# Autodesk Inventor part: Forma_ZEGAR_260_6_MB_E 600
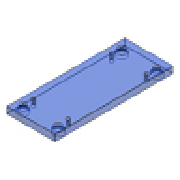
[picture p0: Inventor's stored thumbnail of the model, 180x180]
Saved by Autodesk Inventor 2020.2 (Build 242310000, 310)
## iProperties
Manager: www.cadconsulting.pl
Company: Fabian Stasiak CAD Consulting
Created: 2014-02
Part Number: Forma_ZEGAR_260_6_MB_E 600
Material: S 55 C
Description: Ejector Retainer Plate
Document SubType Name: Modeling
Designer: F.Stasiak
Standard Revision: 1
Manufacturer: DME
Language: pl-PL
Size Designation: 496x218x17
Categories: <MemberInstance><Categories><Category DisplayName="Forma wtryskowa" InternalName="349578f2-f4d4-4954-8c09-8e99297a61c0" Mnemonic="MOLD"><Category DisplayName="P
Density: 7.85 g/cm^3
Appearance: Clear - Blue
Catalog Web Link: www.expertbooks.pl
IsCustomPart: 1
Author: F.Stasiak
Subject: Zbiór ćwiczeń. Autodesk Inventor 2020. Kurs Professional
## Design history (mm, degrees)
sketch "Sketch1"
  geometry: L1 (-109, 248)-(109, 248); L2 (109, 248)-(109, -248); L3 (109, -248)-(-109, -248); L4 (-109, -248)-(-109, 248); 5 further points
  constraints: 8 end point, 2 midpoint, 2 parallel, 1 horizontal, 1 horizontal alignment, 1 perpendicular, 1 vertical alignment
  dimensions: "d84" = 218 distance between parallel lines of L2 L4 (= W_); "d85" = 496 distance between parallel lines of L3 L1 (= L); "d86" = 95 horizontal distance of point (0, 0) point (-95, 233) (= 0.5 x RP_W); "d87" = 233 vertical distance of point (0, 0) point (-95, 233) (= 0.5 x RP_L); "d88" = 95 horizontal distance of point (0, 0) point (-95, 210) (= 0.5 x S2_W); "d89" = 210 vertical distance of point (0, 0) point (-95, 210) (= 0.5 x S2_L)
extrude "Extrusion1" new body sketch "Sketch1" distance "d20" = 17 (= H_); taper "d30" = 0 deg
hole "Hole1" sketch "Sketch1" diameter "d90" = 8.376; stored, may be unused: countersink angle "d94" = 90 deg, drill point angle "d96" = 0 deg; dims "d91" = 6, "d92" = 4, "d93" = 2, "d95" = 17 (= H_)
pattern_linear "Rectangular Pattern1" dims "d106" = 420 (computed from S2_L, Nl), "d109" = 190 (computed from S2_W, Nw)
hole "Hole2" sketch "Sketch1" diameter "d97" = 14 (= RP_d1); stored, may be unused: countersink angle "d101" = 90 deg, drill point angle "d103" = 0 deg; dims "d98" = 6, "d99" = 19 (= RP_d2), "d100" = 4 (= RP_k), "d102" = 17 (= H_)
pattern_linear "Rectangular Pattern2" dims "d112" = 466 (computed from RP_L, Nl), "d115" = 190 (computed from RP_W, Nw)
chamfer "Chamfer1" distance "d116" = 0.5; stored, may be unused: second distance "d117" = 2, angle "d118" = 45 deg
sketch "Szkic13"
  geometry: 1 further point
hole "Otwór19" sketch "Szkic13" at (0, 0) diameter "d196" = 4.5; stored, may be unused: countersink angle "d200" = 90 deg, drill point angle "d202" = 0 deg; dims "d197" = 6, "d198" = 8, "d199" = 3, "d201" = 8
sketch "Szkic14"
  geometry: 4 further points
hole "Otwór20" sketch "Szkic14" at (-54, 134), (-24, -134), (24, 134), (54, -134) diameter "d203" = 5; stored, may be unused: countersink angle "d207" = 90 deg, drill point angle "d209" = 0 deg; dims "d204" = 6, "d205" = 9, "d206" = 3, "d208" = 8
sketch "Szkic15"
  geometry: 4 further points
hole "Otwór21" sketch "Szkic15" at (-24, 134), (-54, -134), (54, 134), (24, -134) diameter "d210" = 5; stored, may be unused: countersink angle "d214" = 90 deg, drill point angle "d216" = 0 deg; dims "d211" = 6, "d212" = 9, "d213" = 3, "d215" = 8
sketch "Szkic16"
  geometry: 4 further points
hole "Otwór22" sketch "Szkic16" at (-54, 103.5), (-24, -103.5), (24, 103.5), (54, -103.5) diameter "d217" = 5; stored, may be unused: countersink angle "d221" = 90 deg, drill point angle "d223" = 0 deg; dims "d218" = 6, "d219" = 9, "d220" = 3, "d222" = 8
sketch "Szkic17"
  geometry: 4 further points
hole "Otwór23" sketch "Szkic17" at (-24, 103.5), (-54, -103.5), (54, 103.5), (24, -103.5) diameter "d224" = 5; stored, may be unused: countersink angle "d228" = 90 deg, drill point angle "d230" = 0 deg; dims "d225" = 6, "d226" = 9, "d227" = 3, "d229" = 8
sketch "Szkic18"
  geometry: 4 further points
hole "Otwór24" sketch "Szkic18" at (-47, 71.2), (-31, -71.2), (31, 71.2), (47, -71.2) diameter "d231" = 5; stored, may be unused: countersink angle "d235" = 90 deg, drill point angle "d237" = 0 deg; dims "d232" = 6, "d233" = 9, "d234" = 3, "d236" = 8
sketch "Szkic19"
  geometry: 4 further points
hole "Otwór25" sketch "Szkic19" at (-31, 71.2), (-47, -71.2), (47, 71.2), (31, -71.2) diameter "d238" = 5; stored, may be unused: countersink angle "d242" = 90 deg, drill point angle "d244" = 0 deg; dims "d239" = 6, "d240" = 9, "d241" = 3, "d243" = 8
sketch "Szkic20"
  geometry: 4 further points
hole "Otwór26" sketch "Szkic20" at (-48.5, 54), (-29.5, -54), (29.5, 54), (48.5, -54) diameter "d245" = 5; stored, may be unused: countersink angle "d249" = 90 deg, drill point angle "d251" = 0 deg; dims "d246" = 6, "d247" = 9, "d248" = 3, "d250" = 8
sketch "Szkic21"
  geometry: 4 further points
hole "Otwór27" sketch "Szkic21" at (-29.5, 54), (-48.5, -54), (48.5, 54), (29.5, -54) diameter "d252" = 5; stored, may be unused: countersink angle "d256" = 90 deg, drill point angle "d258" = 0 deg; dims "d253" = 6, "d254" = 9, "d255" = 3, "d257" = 8
sketch "Szkic22"
  geometry: 4 further points
hole "Otwór28" sketch "Szkic22" at (-57, 29), (-21, -29), (21, 29), (57, -29) diameter "d259" = 5; stored, may be unused: countersink angle "d263" = 90 deg, drill point angle "d265" = 0 deg; dims "d260" = 6, "d261" = 9, "d262" = 3, "d264" = 8
sketch "Szkic23"
  geometry: 4 further points
hole "Otwór29" sketch "Szkic23" at (-39, 35), (-39, -35), (39, 35), (39, -35) diameter "d266" = 5; stored, may be unused: countersink angle "d270" = 90 deg, drill point angle "d272" = 0 deg; dims "d267" = 6, "d268" = 9, "d269" = 3, "d271" = 8
sketch "Szkic24"
  geometry: 4 further points
hole "Otwór30" sketch "Szkic24" at (-21, 29), (-57, -29), (57, 29), (21, -29) diameter "d273" = 5; stored, may be unused: countersink angle "d277" = 90 deg, drill point angle "d279" = 0 deg; dims "d274" = 6, "d275" = 9, "d276" = 3, "d278" = 8
body "Solid1"
other parameters: "L" = 496 [user parameter; used in 1 equation term], "W_" = 218 [user parameter; used in 1 equation term], "H_" = 17 [user parameter; used in 3 equation terms], "RP_k" = 4 [user parameter; used in 1 equation term], "RP_d1" = 14 [user parameter; used in 1 equation term], "RP_d2" = 19 [user parameter; used in 1 equation term], "RP_L" = 466 [user parameter; used in 2 equation terms]
